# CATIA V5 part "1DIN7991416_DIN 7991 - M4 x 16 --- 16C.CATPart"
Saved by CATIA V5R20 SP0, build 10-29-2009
Part number: 1DIN7991416_DIN 7991 - M4 x 16 --- 16C
Revision: ANY
Definition: UNKNOWN
Nomenclature: 1DIN7991416_DIN 7991 - M4 x 16 --- 16C
Source: Unknown
Bounding box of the stored display mesh (mm): x 0 to 16, y -3.633 to 3.633, z -3.82 to 3.82
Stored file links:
  C:\Users\Utente\Desktop\IO LAVORO\3D X SITO CF\CUMSA\3D files PW\pw060622\pw060622_ejection\1DIN7991416_DIN 7991 - M4 x 16 --- 16C.CATPart
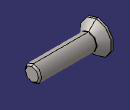
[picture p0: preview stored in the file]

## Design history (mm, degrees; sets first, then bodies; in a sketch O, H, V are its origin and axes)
Body1 "Hex" (main body)
  Solid1: solid without history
